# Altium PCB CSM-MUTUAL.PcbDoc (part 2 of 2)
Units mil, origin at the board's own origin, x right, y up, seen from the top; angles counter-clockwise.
Board outline 5500 x 4000 mil, 2 copper layers (Top Layer, Bottom Layer), stack 62 mil thick; 159 components, 115 nets, 998 pads, 195 vias.
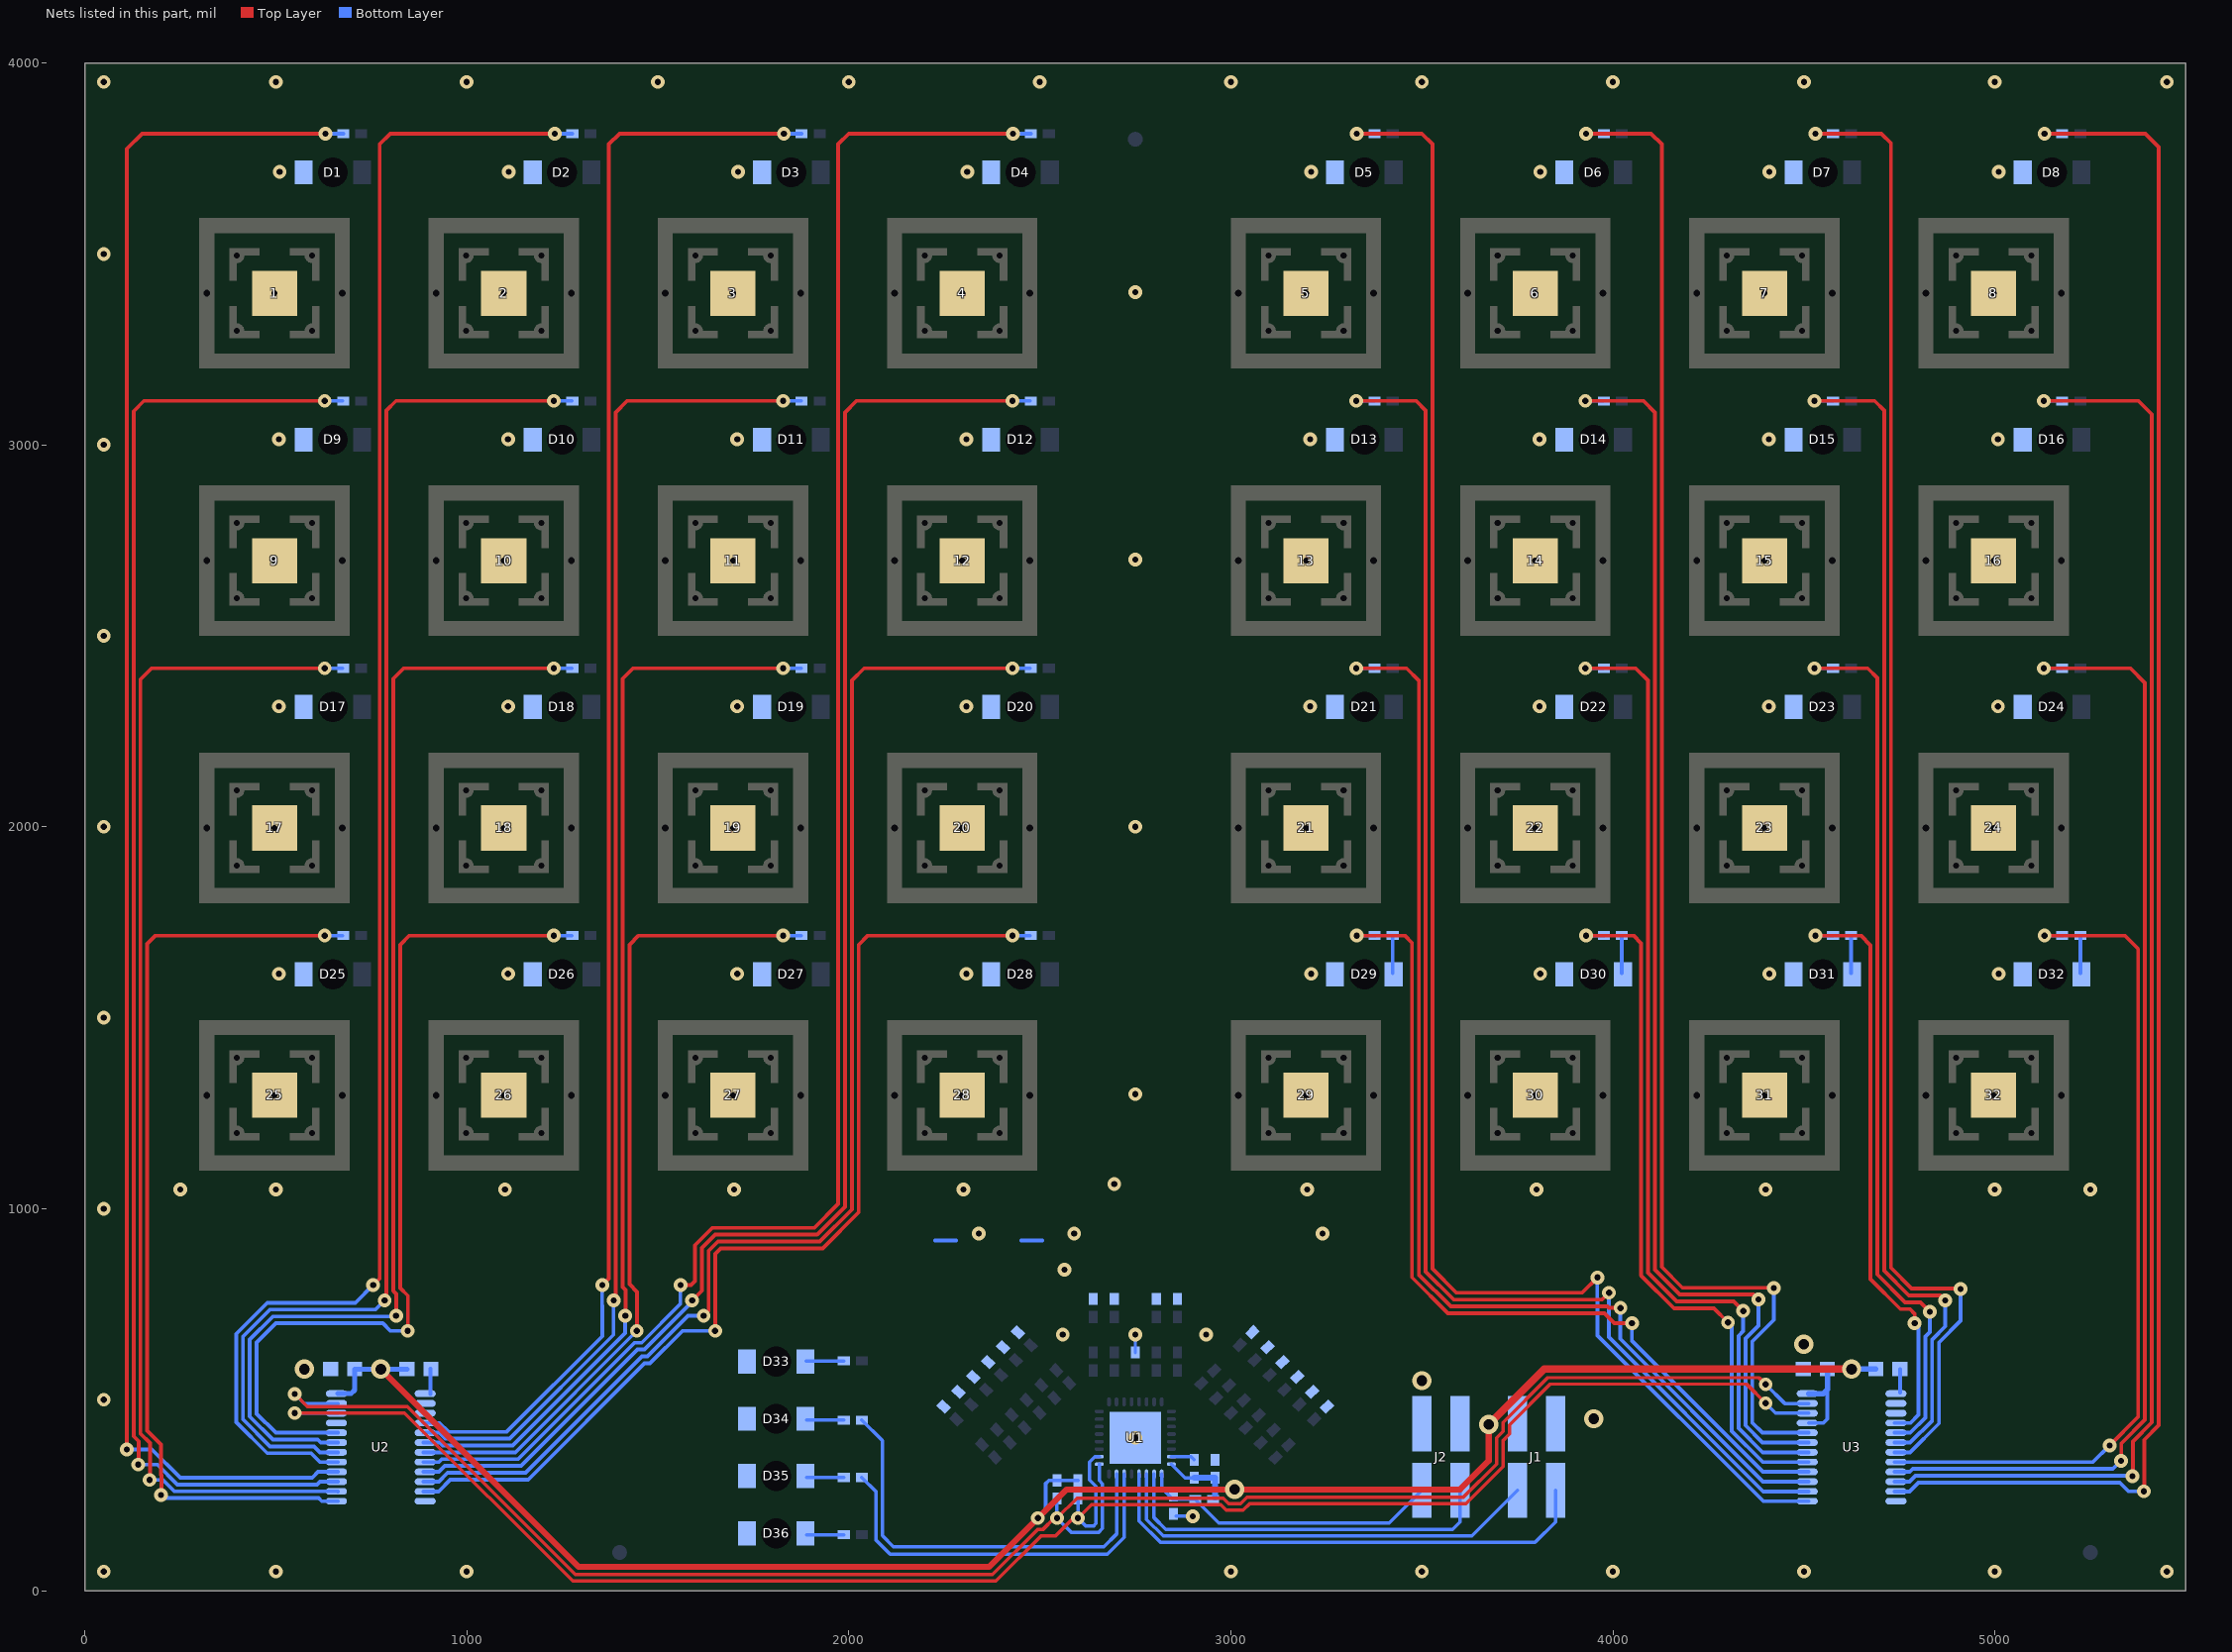
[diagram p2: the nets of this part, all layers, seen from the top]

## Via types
v1: diameter 36, hole 16, Top Layer to Bottom Layer, tented both sides, 186 vias
v2: diameter 50, hole 28, Top Layer to Bottom Layer, tented both sides, 8 vias
v3: diameter 36, hole 16, Top Layer to Bottom Layer, 1 vias

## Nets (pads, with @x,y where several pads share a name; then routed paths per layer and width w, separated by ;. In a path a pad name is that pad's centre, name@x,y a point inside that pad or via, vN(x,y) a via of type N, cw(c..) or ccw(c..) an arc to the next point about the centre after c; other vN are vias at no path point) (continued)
LED29: D29.1 RD29.2 | length 98.7
  Bottom Layer w10: D29.1@3423.62,1616.26 RD29.2@3423.62,1715
LED30: D30.1 RD30.2 | length 98.7
  Bottom Layer w10: D30.1@4023.62,1616.26 RD30.2@4023.62,1715
LED31: D31.1 RD31.2 | length 98.7
  Bottom Layer w10: D31.1@4623.62,1616.26 RD31.2@4623.62,1715
LED32: D32.1 RD32.2 | length 98.7
  Bottom Layer w10: D32.1@5223.62,1616.26 RD32.2@5223.62,1715
NetD33_1: D33.1 RD33.2 | length 98.5
  Bottom Layer w9: D33.1@1888.27,601.5 RD33.2@1986.77,601.5
NetD34_1: D34.1 RD34.2 | length 96.5
  Bottom Layer w9: D34.1@1890.28,446.5 RD34.2@1986.77,446.5
NetD35_1: D35.1 RD35.2 | length 96.5
  Bottom Layer w9: D35.1@1890.28,296.5 RD35.2@1986.77,296.5
NetD36_1: D36.1 RD36.2 | length 96.5
  Bottom Layer w9: D36.1@1890.28,146.5 RD36.2@1986.77,146.5
NetR6_2: R6.2 U2.1 | length 66.6
  Bottom Layer w10: U2.1@905,515 R6.2@905,581.57
NetR7_2: R7.2 U3.1 | length 61.5
  Bottom Layer w10: U3.1@4751.5,518.5 R7.2@4751.5,580
NetRD1_1: RD1.1 U2.16 | length 4577.8
  Top Layer w10: v1(110,370) 110,3775 150,3815 v1(630,3815)
  Bottom Layer w10: v1(110,370) 175.56,370 249.81,295.75 595.75,295.75 611.02,311.02 U2.16@662.8,311.02 ; v1(630,3815) RD1.1@676.38,3815
NetRD2_1: RD2.1 U2.17 | length 4462.3
  Top Layer w10: v1(755,800) 772.13,817.13 772.13,3787.13 800,3815 v1(1230,3815)
  Bottom Layer w10: U2.17@662.8,336.61 615.75,336.61 592.6,359.76 477.79,359.76 396.38,441.18 396.38,672.21 477.79,753.62 708.62,753.62 v1(755,800) ; v1(1230,3815) RD2.1@1276.38,3815
NetRD3_1: RD3.1 U2.4 | length 4225.8
  Top Layer w10: v1(1355,800) 1372.13,817.13 1372.13,3787.13 1400,3815 v1(1830,3815)
  Bottom Layer w10: U2.4@887.2,438.98 928.22,438.98 951.37,415.83 1104.99,415.83 1355,665.83 1355,746.34 1354.13,747.21 1354.13,799.13 v1(1355,800) ; v1(1830,3815) RD3.1@1876.38,3815
NetRD4_1: RD4.1 U2.8 | length 4739.2
  Top Layer w10: v1(1560,800) 1587.25,800 1597.25,810 1597.25,904.46 1642.79,950 1909.72,950 1972.26,1012.54 1972.26,3787.26 2000,3815 v1(2430,3815)
  Bottom Layer w10: U2.8@887.2,336.61 927.28,336.61 935,344.33 1134.61,344.33 1439.4,649.13 1457.79,649.13 1559.13,750.46 1559.13,799.13 v1(1560,800) ; v1(2430,3815) RD4.1@2476.38,3815
NetRD5_1: RD5.1 U3.13 | length 4560.2
  Top Layer w10: v1(3330,3815) 3500,3815 3527.87,3787.13 3527.87,842.4 3590.28,780 3920,780 v1(3960,820)
  Bottom Layer w10: v1(3330,3815) RD5.1@3376.38,3815 ; v1(3960,820) 3959.13,819.13 3959.13,766.34 3960,765.46 3960,668.06 4393.8,234.25 U3.13@4512.8,234.25
NetRD6_1: RD6.1 U3.20 | length 4046.3
  Top Layer w10: v1(3930,3815) 4100,3815 4127.87,3787.13 4127.87,847.4 4182.19,793.08 4420.5,793.08 v1(4421.38,792.21)
  Bottom Layer w10: v1(3930,3815) RD6.1@3976.38,3815 ; v1(4421.38,792.21) 4421.38,708.59 4365,652.21 4365,440 4391.61,413.39 U3.20@4512.8,413.39
NetRD7_1: RD7.1 U3.7 | length 3927.8
  Top Layer w10: v1(4530,3815) 4702.87,3815 4727.87,3790 4727.87,845.04 4782.04,790.87 4909.13,790.87 v1(4910,790)
  Bottom Layer w10: v1(4530,3815) RD7.1@4576.38,3815 ; U3.7@4737.2,362.2 4778.04,362.2 4853.62,437.79 4853.62,650 4910,706.38 v1(4910,790)
NetRD8_1: RD8.1 U3.11 | length 4567.4
  Top Layer w10: v1(5130,3815) 5393.62,3815 5428.62,3780 5428.62,432.79 5390.87,395.04 5390.87,260.87 v1(5390,260)
  Bottom Layer w10: U3.11@4737.2,259.84 4776.85,259.84 4800,282.99 5327.01,282.99 5350,260 v1(5390,260) ; v1(5130,3815) RD8.1@5176.38,3815
NetRD9_1: RD9.1 U2.15 | length 3868.9
  Top Layer w10: v1(140,330) 140.87,330.87 140.87,390.87 127.87,403.87 127.87,3087.87 155,3115 v1(628.03,3115)
  Bottom Layer w10: v1(140,330) 190.28,330 242.4,277.87 607.87,277.87 615.43,285.43 U2.15@662.8,285.43 ; v1(628.03,3115) RD9.1@674.41,3115
NetRD10_1: RD10.1 U2.18 | length 3737.6
  Top Layer w10: v1(785,760) 790,765 790,3090 815,3115 v1(1228.03,3115)
  Bottom Layer w10: U2.18@662.8,362.2 615.43,362.2 600,377.64 485.19,377.64 414.25,448.58 414.25,664.81 485.19,735.75 760.75,735.75 v1(785,760) ; v1(1228.03,3115) RD10.1@1274.41,3115
NetRD11_1: RD11.1 U2.5 | length 3530.5
  Top Layer w10: v1(1385,760) 1390,765 1390,3085 1420,3115 v1(1828.03,3115)
  Bottom Layer w10: U2.5@887.2,413.39 928.54,413.39 943.97,397.95 1112.4,397.95 1384.13,669.68 1384.13,759.13 v1(1385,760) ; v1(1828.03,3115) RD11.1@1874.41,3115
NetRD12_1: RD12.1 U2.9 | length 4031
  Top Layer w10: v1(1590,760) 1615.13,785.13 1615.13,897.06 1650.19,932.13 1917.13,932.13 1990.14,1005.14 1990.14,3085.14 2020,3115 v1(2428.03,3115)
  Bottom Layer w10: U2.9@887.2,311.02 926.97,311.02 942.4,326.46 1142.01,326.46 1446.81,631.25 1465.19,631.25 v1@1590,756.06 ; v1(2428.03,3115) RD12.1@2474.41,3115
NetRD13_1: RD13.1 U3.14 | length 3818.9
  Top Layer w10: v1(3328.03,3115) 3485,3115 3510,3090 3510,835 3583.26,761.74 3919.22,761.74 3971.74,761.74 v1(3990,780)
  Bottom Layer w10: v1(3328.03,3115) RD13.1@3374.41,3115 ; v1(3990,780) 3989.13,779.13 3989.13,664.21 4393.49,259.84 U3.14@4512.8,259.84
NetRD14_1: RD14.1 U3.19 | length 3316.2
  Top Layer w10: v1(3928.03,3115) 4080,3115 4110,3085 4110,840 4174.79,775.21 4368.38,775.21 v1@4380.5,763.08
  Bottom Layer w10: v1(3928.03,3115) RD14.1@3974.41,3115 ; v1(4381.38,762.21) 4381.38,693.87 4347.13,659.61 4347.13,432.6 4391.93,387.8 U3.19@4512.8,387.8
NetRD15_1: RD15.1 U3.6 | length 3133.3
  Top Layer w10: v1(4528.03,3115) 4685,3115 4710,3090 4710,837.64 4774.64,773 4857,773 v1@4869.13,760.87
  Bottom Layer w10: v1(4528.03,3115) RD15.1@4574.41,3115 ; U3.6@4737.2,387.8 4778.35,387.8 4835.75,445.19 4835.75,657.4 4870,691.66 v1(4870,760)
NetRD16_1: RD16.1 U3.10 | length 3772.9
  Top Layer w10: v1(5128.03,3115) 5375.75,3115 5410.75,3080 5410.75,440.19 5360.87,390.32 5360.87,300.87 v1(5360,300)
  Bottom Layer w10: U3.10@4737.2,285.43 4776.97,285.43 4792.4,300.87 v1@5359.13,300.87 ; v1(5128.03,3115) RD16.1@5174.41,3115
NetRD17_1: RD17.1 U2.14 | length 3152.6
  Top Layer w10: v1(170,290) 170.87,290.87 170.87,386.15 145.75,411.28 145.75,2385.75 175,2415 v1(628.03,2415)
  Bottom Layer w10: v1(170,290) 205,290 235,260 662.64,260 U2.14@662.8,259.84 ; v1(628.03,2415) RD17.1@674.41,2415
NetRD18_1: RD18.1 U2.19 | length 3015.5
  Top Layer w10: v1(815,720) 815.87,720.87 815.87,777 807.87,785 807.87,2387.87 835,2415 v1(1228.03,2415)
  Bottom Layer w10: U2.19@662.8,387.8 617.72,387.8 610,395.51 492.6,395.51 432.13,455.98 432.13,657.4 492.6,717.87 v1@812.87,717.87 ; v1(1228.03,2415) RD18.1@1274.41,2415
NetRD19_1: RD19.1 U2.6 | length 2847.3
  Top Layer w10: v1(1415,720) 1415.87,720.87 1415.87,787 1407.87,795 1407.87,2387.87 1435,2415 v1(1828.03,2415)
  Bottom Layer w10: U2.6@887.2,387.8 928.85,387.8 936.57,380.08 1119.8,380.08 1414.13,674.4 1414.13,719.13 v1(1415,720) ; v1(1828.03,2415) RD19.1@1874.41,2415
NetRD20_1: RD20.1 U2.10 | length 3372.5
  Top Layer w10: v1(1620,720) 1633,733 1633,889.66 1657.6,914.25 1924.53,914.25 2008.01,997.74 2008.01,2383.01 2040,2415 v1(2428.03,2415)
  Bottom Layer w10: U2.10@887.2,285.43 926.66,285.43 949.81,308.58 1153.58,308.58 1458.38,613.38 1472.6,613.38 1579.22,720 v1(1620,720) ; v1(2428.03,2415) RD20.1@2474.41,2415
NetRD21_1: RD21.1 U3.15 | length 3072.7
  Top Layer w10: v1(3328.03,2415) 3460,2415 3492.13,2382.87 3492.13,827.6 3575.85,743.87 3911.81,743.87 3985.26,743.87 3989.13,740 v1(4020,740)
  Bottom Layer w10: v1(3328.03,2415) RD21.1@3374.41,2415 ; v1(4020,740) 4019.13,739.13 4019.13,659.49 4393.18,285.43 U3.15@4512.8,285.43
NetRD22_1: RD22.1 U3.18 | length 2586.6
  Top Layer w10: v1(3928.03,2415) 4060,2415 4092.13,2382.87 4092.13,832.6 4167.39,757.34 4316.25,757.34 v1(4341.38,732.21)
  Bottom Layer w10: v1(3928.03,2415) RD22.1@3974.41,2415 ; v1(4341.38,732.21) 4341.38,679.34 4329.25,667.21 4329.25,425.19 4392.24,362.2 U3.18@4512.8,362.2
NetRD23_1: RD23.1 U3.5 | length 2340.7
  Top Layer w10: v1(4528.03,2415) 4667.13,2415 4692.13,2390 4692.13,827.87 4764.87,755.13 4804.87,755.13 v1(4830,730)
  Bottom Layer w10: v1(4528.03,2415) RD23.1@4574.41,2415 ; U3.5@4737.2,413.39 4778.66,413.39 4817.87,452.6 4817.87,665 4830,677.13 v1(4830,730)
NetRD24_1: RD24.1 U3.9 | length 2994.9
  Top Layer w10: v1(5128.03,2415) 5355,2415 5392.87,2377.13 5392.87,447.6 5330.87,385.6 5330.87,340.87 v1(5330,340)
  Bottom Layer w10: U3.9@4737.2,311.02 4777.28,311.02 4785,318.74 5308.74,318.74 v1(5330,340) ; v1(5128.03,2415) RD24.1@5174.41,2415
NetRD25_1: RD25.1 U2.13 | length 2448.4
  Top Layer w10: v1(200,250) 200.87,250.87 200.87,302.79 200,303.66 200,382.3 163.62,418.68 163.62,1693.62 185,1715 v1(628.03,1715)
  Bottom Layer w10: v1(200,250) 207.87,242.13 612.36,242.13 620.24,234.25 U2.13@662.8,234.25 ; v1(628.03,1715) RD25.1@674.41,1715
NetRD26_1: RD26.1 U2.20 | length 2322.3
  Top Layer w10: v1(845,680) 845.87,680.87 845.87,772.28 825.75,792.4 825.75,1690.75 850,1715 v1(1228.03,1715)
  Bottom Layer w10: U2.20@662.8,413.39 500,413.39 450,463.39 450,650 500,700 780,700 800,680 v1(845,680) ; v1(1228.03,1715) RD26.1@1274.41,1715
NetRD27_1: RD27.1 U2.7 | length 2167.6
  Top Layer w10: v1(1445,680) 1445.87,680.87 1445.87,782.28 1425.75,802.4 1425.75,1690.75 1450,1715 v1(1828.03,1715)
  Bottom Layer w10: U2.7@887.2,362.2 1127.2,362.2 v1(1445,680) ; v1(1828.03,1715) RD27.1@1874.41,1715
NetRD28_1: RD28.1 U2.11 | length 2718.3
  Top Layer w10: v1(1650,680) 1650.87,680.87 1650.87,882.25 1665,896.38 1931.93,896.38 2025.89,990.33 2025.89,1690.89 2050,1715 v1(2428.03,1715)
  Bottom Layer w10: U2.11@887.2,259.84 926.34,259.84 957.21,290.71 1160.99,290.71 1465.28,595 1479.5,595 1564.5,680 v1(1650,680) ; v1(2428.03,1715) RD28.1@2474.41,1715
NetRD29_1: RD29.1 U3.16 | length 2350.6
  Top Layer w10: v1(3330,1715) 3455,1715 3474.25,1695.75 3474.25,820.19 3568.45,726 3977.85,726 4003.85,700 v1(4050,700)
  Bottom Layer w10: v1(3330,1715) RD29.1@3376.38,1715 ; v1(4050,700) 4050,653.89 4392.87,311.02 U3.16@4512.8,311.02
NetRD30_1: RD30.1 U3.17 | length 1870.4
  Top Layer w10: v1(3930,1715) 4054.25,1715 4074.25,1695 4074.25,825.19 4159.98,739.46 4264.13,739.46 v1(4301.38,702.21)
  Bottom Layer w10: v1(3930,1715) RD30.1@3976.38,1715 ; v1(4301.38,702.21) 4311.38,692.21 4311.38,417.79 4392.55,336.61 U3.17@4512.8,336.61
NetRD31_1: RD31.1 U3.4 | length 1569.2
  Top Layer w10: v1(4530,1715) 4649.25,1715 4674.25,1690 4674.25,815.75 4752.75,737.25 4777.75,737.25 4790,725 v1(4790,700)
  Bottom Layer w10: v1(4530,1715) RD31.1@4576.38,1715 ; U3.4@4737.2,438.98 4778.98,438.98 4800,460 4800,690 v1(4790,700)
NetRD32_1: RD32.1 U3.8 | length 2217.7
  Top Layer w10: v1(5130,1715) 5340,1715 5375,1680 5375,455 v1(5300,380)
  Bottom Layer w10: U3.8@4737.2,336.61 5256.61,336.61 v1(5300,380) ; v1(5130,1715) RD32.1@5176.38,1715
NOISE: RD35.1 U1.6 | length 1027.9
  Bottom Layer w9: RD35.1@2034.02,296.5 2070.71,259.8 2070.71,133.07 2108.15,95.63 2676.31,95.63 2720.47,139.79 U1.6@2720.47,305.51
RESET: C4.1 J2.2 R1.1 U1.1 | length 792.1
  Bottom Layer w9: U1.1@2818.9,305.51 2818.9,267.6 2847.56,238.94 R1.1@2906.69,238.94 2968.76,176.87 3414.37,176.87 J2.2@3500,262.5
RET: 1.GND 2.GND 3.GND 4.GND 5.GND 6.GND 7.GND 8.GND 9.GND 10.GND 11.GND 12.GND 13.GND 14.GND 15.GND 16.GND 17.GND 18.GND 19.GND 20.GND 21.GND 22.GND 23.GND 24.GND 25.GND 26.GND 27.GND 28.GND 29.GND 30.GND 31.GND 32.GND C1.2 C2.2 C3.2 C4.2 C5.2 C6.2 CE1.2 CE2.2 CE3.2 CE4.2 CE5.2 CE6.2 CE7.2 CE8.2 CE9.2 CE10.2 CE11.2 CE12.2 CE13.2 CE14.2 CE15.2 CE16.2 D1.2 D2.2 D3.2 D4.2 D5.2 D6.2 D7.2 D8.2 D9.2 D10.2 D11.2 D12.2 D13.2 D14.2 D15.2 D16.2 D17.2 D18.2 D19.2 D20.2 D21.2 D22.2 D23.2 D24.2 D25.2 D26.2 D27.2 D28.2 D29.2 D30.2 D31.2 D32.2 D33.2 D34.2 D35.2 D36.2 J1.3 J2.1 U1.31 U1.33 U2.2 U2.3 U2.12 U2.21 U3.2 U3.3 U3.12 | length 262.9
  Bottom Layer w9: C3.2@2750,623.62 v1(2750,670) ; U1.31@2844.49,350.79 2895.71,350.79 C2.2@2903.94,342.56 ; C4.2@2856.38,195 v1(2900,195)
  Bottom Layer w10: 2226,917 2281,917 ; 2451,917 2506,917
  other v1: 50,50 500,50 1000,50 3000,50 3500,50 4000,50 4500,50 5000,50 5450,50 50,500 2560,670 2935,670 2565,840 2340,935 2590,935 3240,935 50,1000 250,1050 500,1050 1100,1050 1700,1050 2300,1050 3200,1050 3800,1050 4400,1050 5000,1050 5250,1050 2695,1065 2750,1300 50,1500 508.03,1615 1108.03,1615 1708.03,1615 2308.03,1615 3210,1615 3810,1615 4410,1615 5010,1615 50,2000 2750,2000 508.03,2315 1108.03,2315 1708.03,2315 2308.03,2315 3208.03,2315 3808.03,2315 4408.03,2315 5008.03,2315 50,2500 2750,2700 50,3000 508.03,3015 1108.03,3015 1708.03,3015 2308.03,3015 3208.03,3015 3808.03,3015 4408.03,3015 5008.03,3015 2750,3400 50,3500 510,3715 1110,3715 1710,3715 2310,3715 3210,3715 3810,3715 4410,3715 5010,3715 50,3950 500,3950 1000,3950 1500,3950 2000,3950 2500,3950 3000,3950 3500,3950 4000,3950 4500,3950 5000,3950 5450,3950
  other v2: 3950,450 3500,550 575,580 4500,645
  other v3: 2750,400
RXD: J1.4 U1.4 | length 1341.3
  Bottom Layer w9: U1.4@2759.84,305.51 2759.84,182.43 2816.02,126.25 3796.26,126.25 3849.99,179.99 J1.4@3849.99,262.5
SCAN: RD34.1 U1.7 | length 1120.8
  Bottom Layer w9: RD34.1@2034.02,446.5 2087.59,392.92 2087.59,144.04 2116.31,115.31 2668.15,115.31 2700.79,147.95 U1.7@2700.79,305.51
SCL: R3.2 U1.10 U2.22 U3.22 | length 4881.2
  Top Layer w9: v1@551.87,463.13 v1(550,465) 837.32,465 1277.32,25 2385,25 2502.75,142.75 2540.71,142.75 2587.96,190 v1(2600,190) 2635.37,225.37 2912.58,225.37 2912.96,225 2973.28,225 2987.53,210.75 3032.47,210.75 3049.47,227.75 3615.43,227.75 3712.25,324.57 3712.25,393.01 3729.25,410.01 3729.25,433.74 3836.26,540.75 4350,540.75 v1(4400,490.75)
  Bottom Layer w9: v1(550,465) U2.22@662.36,465 ; R3.2@2600,241.38 v1(2600,190) 2621.25,168.75 2640,168.75 2647.35,176.1 2647.35,273.01 2630,290.36 2630,336.86 2643.93,350.79 U1.10@2655.51,350.79 ; v1(4400,490.75) 4426.19,464.57 U3.22@4512.8,464.57
SDA: R2.2 U1.9 U2.23 U3.23 | length 4952.3
  Top Layer w9: v1(550,515) 583.13,481.87 844.31,481.87 1284.31,41.87 2375.69,41.87 2493.44,159.63 2507.58,159.63 2537.96,190 v1(2545,190) 2597.25,242.25 2979.9,242.25 2994.52,227.63 3025.48,227.63 3042.48,244.63 3608.44,244.63 3695.37,331.56 3695.37,400 3712.37,417 3712.37,440.73 3829.27,557.63 4382.37,557.63 v1(4400,540)
  Bottom Layer w9: v1(550,515) 575,490 662.64,490 U2.23@662.8,490.16 ; R2.2@2545,241.38 v1(2545,190) 2583.13,151.87 2653.01,151.87 2664.23,163.09 2664.23,280 2655.51,288.72 U1.9@2655.51,331.1 ; v1(4400,540) 4449.84,490.16 U3.23@4512.8,490.16
TEST: J2.4 U1.2 | length 1019.1
  Bottom Layer w9: U1.2@2799.21,305.51 2799.21,190.79 2830,160 3580.01,160 3600,179.99 J2.4@3600,262.5
TXD: J1.2 U1.3 | length 1156.8
  Bottom Layer w9: U1.3@2779.53,305.51 2779.53,186.61 2823.01,143.13 3630.62,143.13 J1.2@3749.99,262.5
VCC: C1.1 C2.1 C5.1 C6.1 J1.1 J2.3 R1.2 R2.1 R3.1 R6.1 R7.1 U1.32 U2.24 U3.21 U3.24 | length 5305.3
  Top Layer w16: v2(775,580) 1292.75,62.25 2367.25,62.25 v1(2495,190) 2570,265 v2(3010,265) 3600,265 3675,340 v2(3675,435)
  Top Layer w20: v2(3675,435) 3820,580 v2(4625,580)
  Bottom Layer w9: U1.32@2844.49,331.1 2880.28,295.32 C2.1@2903.94,295.32
  Bottom Layer w10: v1(2495,190) 2515,210 2515,280 2523.62,288.62 R2.1@2545,288.62 R3.1@2600,288.62 ; U3.21@4512.8,438.98 4550.98,438.98 4561.5,449.49 4561.5,526.5
  Bottom Layer w13: U2.24@662.8,515.75 697.24,515.75 706.5,525 C5.1@706.5,580 v2(775,580) R6.1@843.5,580
  Bottom Layer w14: U3.24@4512.8,515.75 4550.75,515.75 4561.5,526.5 C6.1@4561.5,580 v2(4625,580) R7.1@4688.5,580
  Bottom Layer w16: C2.1@2903.94,295.32 C1.1@2958.94,295.32 R1.2@2958.94,243.94
pads on no net: D1. D2. D3. D4. D5. D6. D7. D8. D9. D10. D11. D12. D13. D14. D15. D16. D17. D18. D19. D20. D21. D22. D23. D24. D25. D26. D27. D28. D29. D30. D31. D32. D33. D34. D35. D36. FID1.1 FID2.1 FID3.1 U1.11 U1.29 U1.30

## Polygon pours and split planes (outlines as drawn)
RET on Bottom Layer "Bottom Layer Return Plane" (solid, remove dead copper, pour order 7): 20,20 5480,20 5480,3980 20,3980 20,20
VCC on Bottom Layer "MCU VCC Plane" (solid, remove dead copper, pour order 8): 2892,311 2892,272.75 2904,260.75 2928,260.75 2938,250.75 2938,227.13 3016.38,227.13 3040,250.75 3040,282 3028,294 3009,294 2990,294 2972,312 2971,311 2892,311
VCC on Bottom Layer "VCC Plane" (solid, remove dead copper, pour order 5): 3775,510 3575,510 3575,365 3775,365 3775,510
RET on Top Layer "Top Layer Return Plane" (solid, remove dead copper, pour order 6): 20,20 5480,20 5480,3980 20,3980 20,20

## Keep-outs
Keep-Out Layer:
  text ".Layer_Name" at 577,-858.49 h60

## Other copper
Top Layer:
  text ".Layer_Name" at 577,-858.49 h60
Bottom Layer:
  region net VCC: 3775,365 3575,365 3575,510 3775,510
  text ".Layer_Name" at 577,-858.49 h60

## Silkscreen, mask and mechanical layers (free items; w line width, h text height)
Top Overlay:
  lines w25: 50,450 1500,450 ccw(c1500,600) 1650,600 cw(c1800,600) 1800,750 3700,750 cw(c3700,600) 3850,600 ccw(c4000,600) 4000,450 5450,450
  text "Detection" at 1970,560 h125
  text "CSM-MUTUAL" at 2700,480 h150
  text "Run" at 1970,410 h125
  text "TM" at 4930,265 h60
  text "Noise" at 1970,260 h125
  text "TIDM-CAPTOUCHEMCREF" at 2580,260 h100
  text "MSP CapTIvate  MCUs" at 3990,175 h150
  text "Capacitive Sensing Module" at 2570,160 h100
  text "Fault" at 1970,110 h125
  text ".Layer_Name" at 577,-858.49 h60
Bottom Overlay:
  text "TM" at 4190,1200 h70
  text "MSP CapTIvate  MCUs" at 5300,1120 h175
  text "Capacitive Touch MCU TI Design" at 5300,1000 h125
  text "www.ti.com/captivate" at 5300,890 h125
  text ".PRJ_Number" at 5300,780 h125
  text "VCC" at 3625,680 h75 r90
  text "VCC" at 3775,680 h75 r90
  text "RET" at 3525,670 h75 r90
  text "RET" at 3875,670 h75 r90
  text ".PCB_Rev" at 4840,670 h125
  text "Revision" at 5300,670 h125
  text "RST" at 3525,160 h75 r90
  text "TST" at 3625,160 h75 r90
  text "TXD" at 3775,160 h75 r90
  text "RXD" at 3875,160 h75 r90
  text ".Layer_Name" at 577,-858.49 h60
Top Paste:
  text ".Layer_Name" at 577,-858.49 h60
Bottom Paste:
  text ".Layer_Name" at 577,-858.49 h60
Top Solder:
  text ".Layer_Name" at 577,-858.49 h60
  text ".Layer_Name" at 577,-858.49 h60
Bottom Solder:
  text ".Layer_Name" at 577,-858.49 h60
Drill Guide:
  text ".Layer_Name" at 577,-858.49 h60
M1 Board Outline:
  the board outline again, w15
  text ".Layer_Name" at 577,-858.49 h60
M2 Board Dimensions:
  rectangle: 125,-400 500,-275
  rectangle: 0,-275 125,-150
  lines w7: 0,-275 1000,-275 ; 0,-150 0,-400 1000,-400 1000,-150 ; 125,-400 125,-150 ; 250,-400 250,-150 ; 500,-400 500,-150 ; 750,-400 750,-150
  text ".Layer_Name" at 577,-858.49 h60
M3 3D STEP Top:
  text ".Layer_Name" at 577,-858.49 h60
M4 3D STEP Bottom:
  text ".Layer_Name" at 577,-858.49 h60
M5 Assembly Top:
  lines w10: -292,-523.5 -292,-1133.5 3713,-1133.5 ; 1284,-1133.5 -291.5,-1133.5 -291.5,-523.5 ; 2173,-1133.5 2173,-523.5 ; 3440,-726.83 3440,-523.5 ; 4280,-726.83 4280,-523.5 ; 4902,-1140 4902,-937.17 ; -292,-930.17 6308,-930.17 ; -292,-930.17 6308,-930.17 ; -292,-930.17 6308,-930.17 ; -292,-726.83 6310,-726.83 ; -292,-726.83 6310,-726.83 ; -292,-726.83 6310,-726.83 ; -291.5,-523.5 6310,-523.5 ; -291.5,-523.5 6310,-523.5 ; -291.5,-523.5 6310,-523.5 ; 3713,-1133.5 6310,-1133.5 ; 3713,-1133.5 6310,-1133.5 ; 3713,-1133.5 6310,-1133.5 ; 6310,-1133.5 6310,-523.5 ; 6310,-1133.5 6310,-523.5 ; 6310,-1133.5 6310,-523.5
  text "COMPONENTS MARKED 'DNP' SHOULD NOT BE POPULATED." at 1153.5,-318.5 h60
  text "ASSEMBLY VARIANT:" at 1153,-434 h60
  text ".VariantName" at 2189,-434 h60
  text "PCB VIEWED FROM TOP SIDE" at -228.5,-655.67 h60
  text "BOARD #:" at 2248,-655.67 h60
  text ".PRJ_Number" at 2793.5,-655.67 h60
  text "REV:" at 3638,-655.67 h60
  text ".PCB_Rev" at 3929.5,-655.67 h60
  text "SVN REV:" at 4476,-655.67 h60
  text ".VersionControl_RevNumber" at 4982,-655.67 h60
  text "TID #:" at 2248,-859 h60
  text ".TID" at 2793.5,-859 h60
  text "PLOT NAME =" at -228.5,-1064.34 h60
  text ".plot_File_Name" at 577,-1064.34 h60
  text "GENERATED    :" at 2250,-1064.34 h60
  text ".Print_Date" at 3119.5,-1064.34 h60
  text ".Print_Time" at 3848.5,-1064.34 h60
  text "TEXAS INSTRUMENTS" at 5113,-1064.34 h60
M6 Assembly Bottom:
  lines w10: 1115.5,-1140.5 1115.5,-937.67 ; 1737.5,-727.33 1737.5,-524 ; 2577.5,-727.33 2577.5,-524 ; 3844.5,-1134 3844.5,-524 ; -292.5,-727.33 6309.5,-727.33 ; -292.5,-727.33 6309.5,-727.33 ; -292.5,-727.33 6309.5,-727.33 ; -292.5,-524 6309,-524 ; -292.5,-524 6309,-524 ; -292.5,-524 -292.5,-1134 2304.5,-1134 ; -292.5,-524 6309,-524 ; -290.5,-930.67 6309.5,-930.67 ; -290.5,-930.67 6309.5,-930.67 ; -290.5,-930.67 6309.5,-930.67 ; 2304.5,-1134 6309.5,-1134 ; 2304.5,-1134 6309.5,-1134 ; 2304.5,-1134 6309.5,-1134 ; 4733.5,-1134 6309,-1134 ; 4733.5,-1134 6309,-1134 ; 4733.5,-1134 6309,-1134 ; 6309,-1134 6309,-524 ; 6309,-1134 6309,-524 ; 6309,-1134 6309,-524 ; 6309.5,-1134 6309.5,-524 ; 6309.5,-1134 6309.5,-524 ; 6309.5,-1134 6309.5,-524
  text "COMPONENTS MARKED 'DNP' SHOULD NOT BE POPULATED." at 6102,-318 h60
  text ".VariantName" at 5058,-434 h60
  text "ASSEMBLY VARIANT:" at 6097,-434 h60
  text ".VersionControl_RevNumber" at 1035.5,-656.17 h60
  text "SVN REV:" at 1541.5,-656.17 h60
  text ".PCB_Rev" at 2088,-656.17 h60
  text "REV:" at 2379.5,-656.17 h60
  text ".PRJ_Number" at 3224,-656.17 h60
  text "BOARD #:" at 3769.5,-656.17 h60
  text "PCB VIEWED FROM BOTTOM SIDE" at 6246,-656.17 h60
  text ".TID" at 3224,-859.5 h60
  text "TID #:" at 3769.5,-859.5 h60
  text "TEXAS INSTRUMENTS" at 904.5,-1064.84 h60
  text ".Print_Time" at 2169,-1064.84 h60
  text ".Print_Date" at 2898,-1064.84 h60
  text "GENERATED    :" at 3767.5,-1064.84 h60
  text ".plot_File_Name" at 5440.5,-1064.84 h60
  text "PLOT NAME =" at 6246,-1064.84 h60
M9 Title Sheet:
  drawing of 59 lines, arcs and shapes, not listed
  text "1" at 739.84,8036.5 h70
  text "2" at 3235.5,8036.5 h70
  text "3" at 5724.84,8036.5 h70
  text "4" at 8231.51,8036.5 h70
  text "5" at 10730.5,8036.5 h70
  text "6" at 13235.5,8036.5 h70
  text "A" at -416.5,6893.5 h70
  text "A" at 14383.5,6893.5 h70
  text "B" at -416.5,4513.5 h70
  text "B" at 14383.5,4513.5 h70
  text "C" at -416.5,2138.5 h70
  text "C" at 14383.5,2138.5 h70
  text "PROJECT TITLE:" at 11343.5,277.5 h45
  text ".PRJ_Title" at 11393.5,144.17 h70
  text "DESIGNED FOR:" at 11343.5,-23.5 h45
  text ".PRJ_Customer" at 11393.5,-163.5 h70
  text "D" at -416.5,-231.5 h70
  text "D" at 14383.5,-231.5 h70
  text "FILE NAME:" at 11343.5,-323.5 h45
  text ".PCB_File_Name_No_Path" at 11393.5,-443.5 h70
  text "Texas Instruments (TI) and/or its licensors do not warrant the accuracy or completeness of this specification" at 6374,-605.34 h45
  text "ENGINEER:" at 11343.5,-613.5 h45
  text "LAYOUT BY:" at 12848.5,-613.5 h45
  text "or any information contained therein. TI and/or its licensors do not warrant that this design will meet" at 6329.01,-718 h45
  text ".PRJ_Engineer" at 11393.5,-768.49 h70
  text ".PCB_Layout" at 12899,-768.49 h70
  text "the specifications, will be suitable for your application or fit for any particular purpose, or will operate in" at 6329.01,-830.67 h45
  text ".Layer_Name" at 577,-858.49 h60
  text "ALTIUM DESIGNER VERSION:" at 12848.5,-923.5 h45
  text "an implementation. TI and/or its licensors do not warrant that the design is production worthy. You should" at 6329.01,-943.33 h45
  text "completely validate and test your design implementation to confirm the system functionality for your application." at 6374,-1056 h45
  text ".print_Scale" at 11393.5,-1056.83 h70
  text ".Application_BuildNumber" at 12899,-1056.83 h70
  text "1" at 739.84,-1263.5 h70
  text "2" at 3235.5,-1263.5 h70
  text "3" at 5724.84,-1263.5 h70
  text "4" at 8231.51,-1263.5 h70
  text "5" at 10730.5,-1263.5 h70
  text "6" at 13235.5,-1263.5 h70
M10 Fab Notes:
  drawing of 185 lines, arcs and shapes, not listed
  text "DESIGN INFORMATION" at 12381.02,5910 h60
  text "MIN. TRACK WIDTH:" at 11736.46,5730 h60
  text "8" at 12832.7,5730 h60
  text "MIL" at 12987.46,5730 h60
  text "MIN. CLEARANCE:" at 11736.46,5598 h60
  text "0.2" at 12772.7,5598 h60
  text "mm" at 12987.46,5598 h60
  text "MIN. VIA PAD SIZE:" at 11736.46,5466 h60
  text "24" at 12802.71,5466 h60
  text "MIL" at 12987.46,5466 h60
  text "0.05mm (2MIL)" at 12431.46,5324.29 h60
  text "MINIMUM ANNULAR RING" at 11407.23,5320 h60
  text "EXTERNAL" at 13139.46,5320 h60
  text "PER" at 11607.23,5202 h60
  text "IPC-D-275 CLASS 2 LEVEL C" at 11827.23,5202 h60
  text "MIL, HOLES" at 13315.46,5089.71 h60
  text "+/-" at 12923,5089 h60
  text "+/-" at 13777,5089 h60
  text "REGISTRATION TOLERANCES:" at 11407.23,5084 h60
  text "METAL" at 12607,5084 h60
  text "5" at 13183.2,5084 h60
  text "3" at 14016.2,5084 h60
  text "MIL" at 14132.46,5084 h60
  text "MATERIAL:" at 11332.46,4874.54 h60
  text "FR-4 High Tg" at 12318.9,4734.21 h60
  text "FR-408" at 11753.46,4725.64 h60
  text "X" at 12165.46,4725.64 h60
  text "OTHER" at 13241.46,4725.64 h60
  text "62 MIL (1.6mm) +/-10%" at 12073.56,4562.92 h60
  text "THICKNESS:" at 11407.23,4558.64 h60
  text "X" at 11945.4,4558.64 h60
  text "OTHER" at 13358.46,4558.64 h60
  text "TOLERANCE:" at 11407.23,4400.64 h60
  text "X" at 12246.53,4400.64 h60
  text "ANSI IPC-6012 TYPE 3 CLASS 2" at 12433.48,4400.64 h60
  text "OTHER +/-" at 12433.46,4244.64 h60
  text "BOW & TWIST:" at 11407.23,4087.64 h60
  text "X" at 12246.53,4087.64 h60
  text "ANSI IPC-6012 TYPE 3 CLASS 2" at 12433.48,4087.64 h60
  text "OTHER +/-" at 12433.46,3929.13 h60
  text "DRILLING:" at 11332.46,3790.64 h60
  text "REFERENCE:" at 11407.23,3673.64 h60
  text "X" at 12055.46,3673.64 h60
  text "AS SHOWN" at 12242.46,3673.64 h60
  text "X" at 12956.46,3673.64 h60
  text "NC_DRILL FILES" at 13093.46,3673.64 h60
  text "PTH MIN COPPER THICKNESS:" at 11407.23,3515.64 h60
  text "X" at 12757.46,3515.64 h60
  text "1MIL" at 12894.46,3515.64 h60
  text "OTHER" at 13391.46,3515.64 h60
  text "BOARD FINISH:" at 11332.46,3356.64 h60
  text "SILKSCREEN:" at 11487.68,3238.64 h60
  text "X" at 12436.46,3238.64 h60
  text "TOP" at 12562.46,3238.64 h60
  text "X" at 12946.46,3238.64 h60
  text "BOTTOM" at 13073.46,3238.64 h60
  text "SILKSCREEN COLOR:" at 11487.68,3071.64 h60
  text "X" at 12435.42,3071.64 h60
  text "WHITE" at 12562.46,3071.64 h60
  text "OTHER" at 13073.46,3071.64 h60
  text "SOLDER RESIST COLOR:" at 11487.68,2901.64 h60
  text "X" at 12055.42,2742.44 h60
  text "GREEN" at 12182.46,2742.44 h60
  text "BLUE" at 12773.46,2742.44 h60
  text "OTHER" at 13311.46,2742.44 h60
  text "IMMERSION GOLD (ENIG)" at 12393.46,2553.92 h60
  text "ENEPIG" at 13731,2550.64 h60
  text "SURFACE FINISH:" at 11332.46,2549.64 h60
  text "X" at 12206.51,2549.64 h60
  text "IMM. TIN/SILVER OR EQUIV" at 11662,2392.64 h60
  text "OTHER" at 13093.46,2392.64 h60
  text "ARRAY/PANEL:" at 11332.46,2213.64 h60
  text "CUT AND TRIM PER MECH LAYER 1" at 12393.46,2209.35 h60
  text "N.C. ROUTE" at 12393.46,2057.64 h60
  text "X" at 13072.46,2057.64 h60
  text "V. SCORE" at 13259.46,2057.64 h60
  text "CERTIFICATION:" at 11332.46,1920.64 h60
  text "MATERIALS AND WORKMANSHIP FOR ALL PCBS" at 12057.46,1920.64 h60
  text "TO MEET OR EXCEED THE REQUIREMENTS OF:" at 12057.46,1822.64 h60
  text "X" at 11683.96,1686.13 h60
  text "ANSI IPC-A-600F CLASS ->" at 11822.96,1686.13 h60
  text "X" at 13462.02,1686.13 h60
  text "2" at 13580.96,1686.14 h60
  text "1" at 13265.96,1684.64 h60
  text "3" at 13934.96,1684.64 h60
  text "X" at 11686.02,1526.64 h60
  text "UL 94V-0" at 11822.96,1526.64 h60
  text "X" at 12498.02,1526.64 h60
  text "RoHS" at 12634.96,1526.64 h60
  text "OTHER" at 13279.36,1526.64 h60
  text "PER ORDER" at 13676.42,1526.64 h60
  text "ADDITIONAL REQUIREMENTS:" at 11332.46,1385.64 h60
  text "MICROSECTION:" at 11407.23,1270.64 h60
  text "YES" at 12312.96,1270.64 h60
  text "REQUIRED" at 13174.46,1114.49 h60
  text "BARE BOARD ELEC. TEST:" at 11407.23,1111.64 h60
  text "NONE" at 12712.96,1111.64 h60
  text "X" at 13047.46,1111.64 h60
  text "PER ORDER" at 13766.46,1111.64 h60
  text "MANUFACTURER'S UL:" at 11407.23,954.64 h60
  text "RAIL" at 12572.96,950.35 h60
  text "METAL" at 13064.77,950.35 h60
  text "X" at 13440,950 h60
  text "SILK" at 13576.46,950.35 h60
  text ".Layer_Name" at 577,-858.49 h60
M11 Gerber Information:
  lines w10: -292,-523.5 -292,-1133.5 3713,-1133.5 ; 1284,-1133.5 -291.5,-1133.5 -291.5,-523.5 ; 2173,-1133.5 2173,-523.5 ; 3440,-726.83 3440,-523.5 ; 4280,-726.83 4280,-523.5 ; 4902,-1140 4902,-937.17 ; -292,-930.17 6308,-930.17 ; -292,-930.17 6308,-930.17 ; -292,-930.17 6308,-930.17 ; -292,-726.83 6310,-726.83 ; -292,-726.83 6310,-726.83 ; -292,-726.83 6310,-726.83 ; -291.5,-523.5 6310,-523.5 ; -291.5,-523.5 6310,-523.5 ; -291.5,-523.5 6310,-523.5 ; 3713,-1133.5 6310,-1133.5 ; 3713,-1133.5 6310,-1133.5 ; 3713,-1133.5 6310,-1133.5 ; 6310,-1133.5 6310,-523.5 ; 6310,-1133.5 6310,-523.5 ; 6310,-1133.5 6310,-523.5
  text "ALL ARTWORK VIEWED FROM TOP SIDE" at -228.5,-655.67 h60
  text "BOARD #:" at 2248,-655.67 h60
  text ".PRJ_Number" at 2793.5,-655.67 h60
  text "REV:" at 3638,-655.67 h60
  text ".PCB_Rev" at 3929.5,-655.67 h60
  text "SVN REV:" at 4476,-655.67 h60
  text ".VersionControl_RevNumber" at 4982,-655.67 h60
  text "LAYER NAME =" at -228.5,-858.49 h60
  text "TID #:" at 2248,-859 h60
  text ".TID" at 2793.5,-859 h60
  text "PLOT NAME =" at -228.5,-1064.34 h60
  text ".plot_File_Name" at 577,-1064.34 h60
  text "GENERATED    :" at 2250,-1064.34 h60
  text ".Print_Date" at 3119.5,-1064.34 h60
  text ".Print_Time" at 3848.5,-1064.34 h60
  text "TEXAS INSTRUMENTS" at 5113,-1064.34 h60
M12 Stackup:
  drawing of 191 lines, arcs and shapes, not listed
  text "Layer" at 9790.34,7830 h60
  text "Name" at 10200.26,7830 h60
  text "Material" at 11130,7830 h60
  text "Thickness" at 11989.77,7830 h60
  text "Constant" at 12639.6,7830 h60
  text "Board Layer Stack" at 13209.46,7830 h60
  text "1" at 9790.34,7710 h60
  text "Top Overlay" at 10200.26,7710 h60
  text "2" at 9790.34,7590 h60
  text "Top Solder" at 10200.26,7590 h60
  text "Solder Resist" at 11130,7590 h60
  text "0.40mil" at 11989.77,7590 h60
  text "3.5" at 12639.6,7590 h60
  text "3" at 9790.34,7470 h60
  text "Top Layer" at 10200.26,7470 h60
  text "Copper" at 11130,7470 h60
  text "1.40mil" at 11989.77,7470 h60
  text "4" at 9790.34,7350 h60
  text "Dielectric1" at 10200.26,7350 h60
  text "FR-4" at 11130,7350 h60
  text "59.20mil" at 11989.77,7350 h60
  text "4.8" at 12639.6,7350 h60
  text "5" at 9790.34,7230 h60
  text "Bottom Layer" at 10200.26,7230 h60
  text "Copper" at 11130,7230 h60
  text "1.40mil" at 11989.77,7230 h60
  text "6" at 9790.34,7110 h60
  text "Bottom Solder" at 10200.26,7110 h60
  text "Solder Resist" at 11130,7110 h60
  text "0.40mil" at 11989.77,7110 h60
  text "3.5" at 12639.6,7110 h60
  text "7" at 9790.34,6990 h60
  text "Bottom Overlay" at 10200.26,6990 h60
  text ".Layer_Name" at 577,-858.49 h60
M13 Component Bodies Top:
  text ".Layer_Name" at 577,-858.49 h60
M14 Component Bodies Bottom:
  text ".Layer_Name" at 577,-858.49 h60
M15 Courtyards Top:
  text ".Layer_Name" at 577,-858.49 h60
M16 Courtyards Bottom:
  text ".Layer_Name" at 577,-858.49 h60
Drill Drawing:
  text ".Layer_Name" at 577,-858.49 h60

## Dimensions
0,4000 to 5500,4000 on M2 Board Dimensions
5500,4000 to 5500,0 on M2 Board Dimensions
0,-400 to 1000,-400 on M2 Board Dimensions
